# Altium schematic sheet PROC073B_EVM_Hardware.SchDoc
size 431 x 279 mm; Date: Not shown in title block; ApprovedBy: Not shown in title block; CheckedBy: Not shown in title block; Author: Not shown in title block; CompanyName: Not shown in title block; Engineer: Not shown in title block; Organization: Not shown in title block; Address1: Not shown in title block; Address2: Not shown in title block; Address3: Not shown in title block; Address4: Not shown in title block; DocumentNumber: 1; Revision: Use project parameter SCH_Rev; SheetNumber: 9; SheetTotal: 9; PageSetup: Record=PageOptions¦CenterHorizontal=True¦CenterVertical=True¦PrintScale=1.00¦XCorrection=1.00¦YCorrection=1.00¦PrintKind=0¦BorderSize=5000000¦LeftOffset=0¦BottomOffset=0¦Orientation=2¦PaperLength=1000¦PaperWidth=1000¦Scale=100¦PaperSource=15¦PrintQuality=600¦MediaType=1¦DitherType=10¦PaperKind=Letter¦PrintScaleMode=1
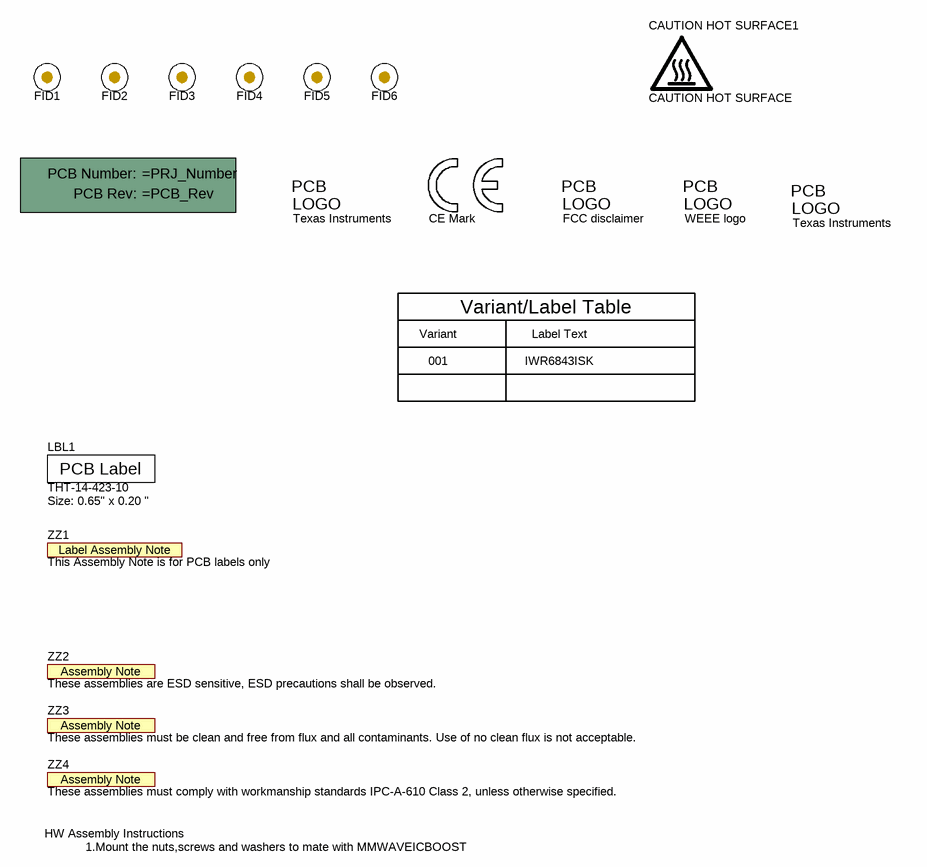
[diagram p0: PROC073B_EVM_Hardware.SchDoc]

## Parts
!PCB  Printed Circuit Board  (value not drawn)  (mechanical)
CAUTION_HOT_SURFACE1  CAUTION HOT SURFACE  [IEC_HotSurface_Small]  (no BOM)
FID1  Fiducial  [Fiducial10-20]  (value not drawn)
FID2  Fiducial  [Fiducial10-20]  (value not drawn)
FID3  Fiducial  [Fiducial10-20]  (value not drawn)
FID4  Fiducial  [Fiducial10-20]  (value not drawn)
FID5  Fiducial  [Fiducial10-20]  (value not drawn)
FID6  Fiducial  [Fiducial10-20]  (value not drawn)
LBL1  THT-14-423-10  Note: Size: 0.65" x 0.20 "  [Label_650x200]
Logo1  Texas Instruments  [TI_Stacked_Overlay_Small]  (no BOM)
Logo2  CE Mark  [CE_Mark_5mm]  (no BOM)
Logo3  FCC disclaimer  [FCC_disclaimer]  (no BOM)
Logo4  WEEE logo  [WEEE_Minimum]  (no BOM)
Logo5  Texas Instruments  [TI_Symbol_Overlay_Small]  (no BOM)
ZZ1  This Assembly Note is for PCB labels only  [AssemblyNoteLabel]  (no BOM)
ZZ2  These assemblies are ESD sensitive, ESD precautions shall be observed.  [AssemblyNote]  (no BOM)
ZZ3  These assemblies must be clean and free from flux and all contaminants. Use of no clean flux is not acceptable.  [AssemblyNote]  (no BOM)
ZZ4  These assemblies must comply with workmanship standards IPC-A-610 Class 2, unless otherwise specified.  [AssemblyNote]  (no BOM)

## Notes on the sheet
- Variant
- 001
- Variant/Label Table
- Label Text
- IWR6843ISK
- (near ZZ4) HW Assembly Instructions
- 1.Mount the nuts,screws and washers to mate with MMWAVEICBOOST

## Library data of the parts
!PCB = CMP-0003618-2: Manufacturer: Any
CAUTION_HOT_SURFACE1 = CMP-0074837-1: IEC 61010-1 Hot Surface Warning; Library Reference: IEC_HotSurface; SymbolCreator: a0412235
FID1-FID6 = CMP-0077181-1: Fiducial mark.  There is nothing to buy or mount.
LBL1 = CMP-0003625-1: Thermal Transfer Printable Labels, 0.650" W x 0.200" H - 10,000 per roll; Manufacturer: Brady; CompType: Label
Logo1 = CMP-0074838-1: Texas Instrument Corporate Signature; SymbolCreator: a0412235; Lib Reference: TI_Logo; Library Reference: Logo
Logo2 = CMP-0074844-1: SymbolCreator: a0412235
Logo3 = CMP-0074847-1: FCC_disclaimer; Library Reference: Logo
Logo4 = CMP-0074769-1
Logo5 = CMP-0074838-1: Texas Instrument Corporate Signature; Library Reference: Logo; SymbolCreator: a0412235; Lib Reference: TI_Logo
ZZ1 = CMP-0003616-3
ZZ2 = CMP-0077236-1
ZZ3 = CMP-0077237-1
ZZ4 = CMP-0077238-1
